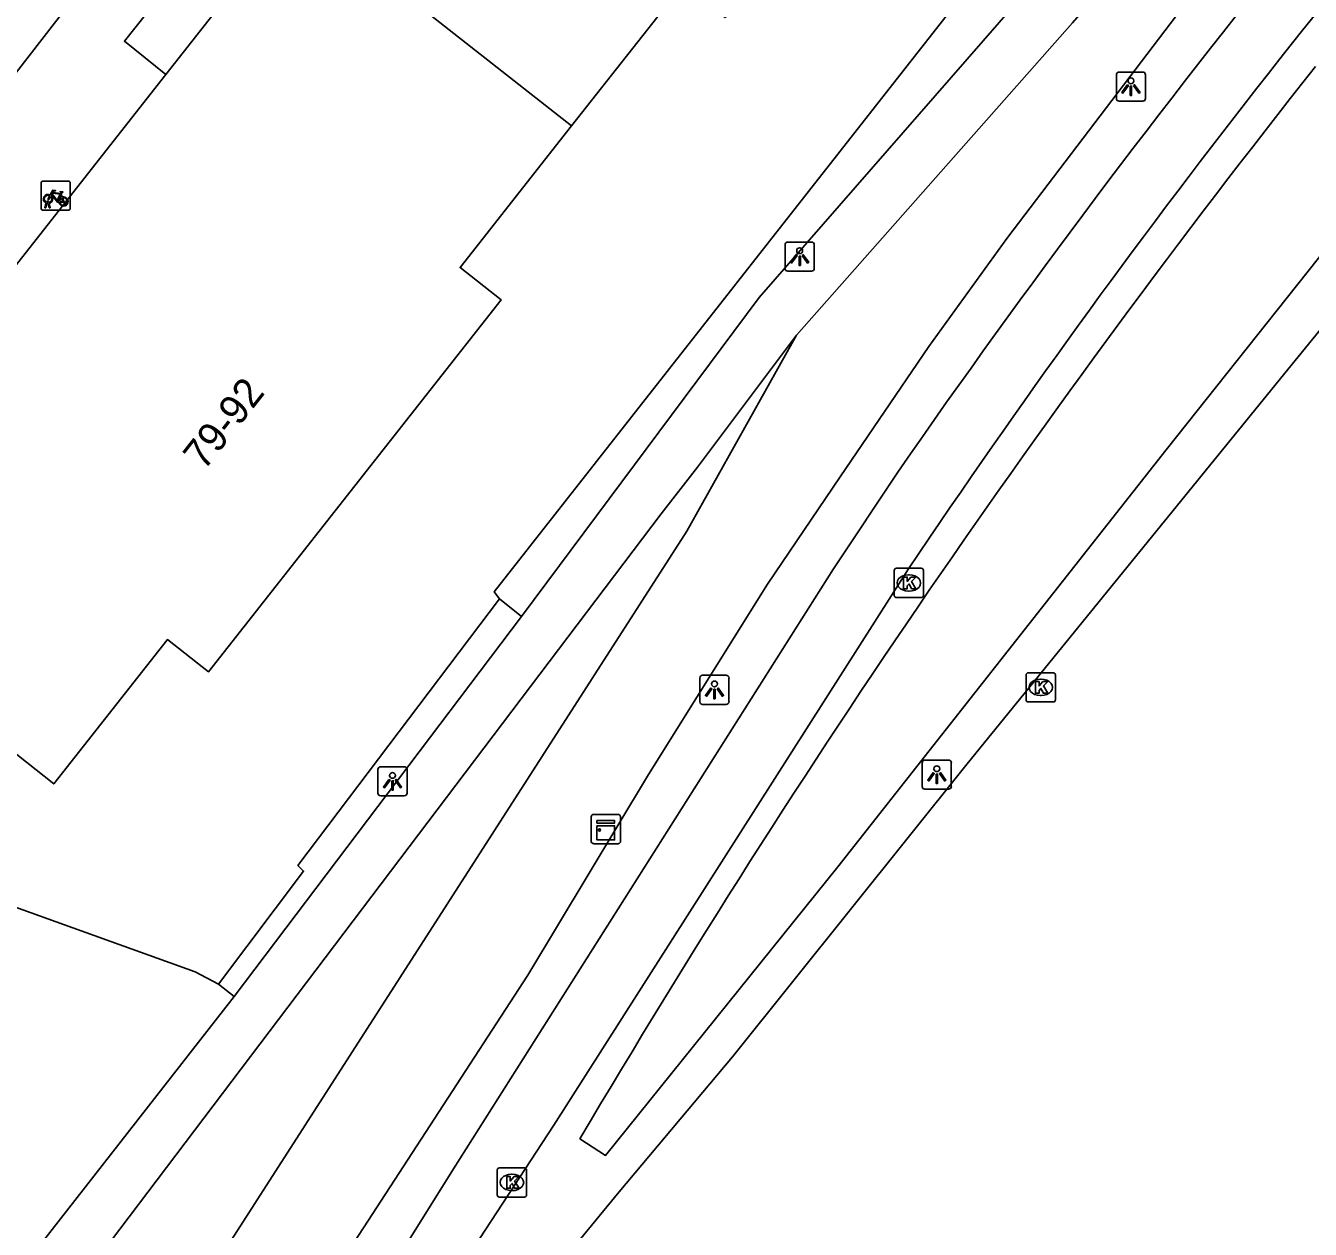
# Model space of a CAD drawing. Extents: x 160304 to 160954, y 383686 to 384161.
# Drawn here: x 160814.08 to 160858.01, y 383754.16 to 383795.32 of the extents above; entities that cross this region are included whole.
import ezdxf

# ---------------------------------------------------------------- set-up
doc = ezdxf.new("R2010")
doc.units = 0
for name, color, linetype in [('IMGEO_Fietsenrek', 7, 'Continuous'), ('IMGEO_Fietspad_open', 7, 'Continuous'), ('IMGEO_Groenvoorziening', 7, 'Continuous'), ('IMGEO_Kast', 7, 'Continuous'), ('IMGEO_Kolk', 7, 'Continuous'), ('IMGEO_Lichtpunt', 7, 'Continuous'), ('IMGEO_Pand', 7, 'Continuous'), ('IMGEO_Pand_nummerreeks', 7, 'Continuous'), ('IMGEO_Rijbaan_lokaal_gesloten', 7, 'Continuous'), ('IMGEO_Voetpad_open', 7, 'Continuous')]:
    doc.layers.add(name, color=color, linetype=linetype)

msp = doc.modelspace()

# ---------------------------------------------------------------- linework, layer by layer
at = {"layer": 'IMGEO_Fietsenrek'}
for p, q in [((160814.608, 383789.086), (160814.608, 383789.927)), ((160814.608, 383789.927), (160814.608, 383789.086)), ((160814.683, 383790.011), (160815.524, 383790.011)), ((160815.524, 383790.011), (160814.683, 383790.011)), ((160815.608, 383789.936), (160815.608, 383789.095)), ((160815.608, 383789.095), (160815.608, 383789.936)), ((160815.295, 383789.56), (160815.331, 383789.465)), ((160815.533, 383789.011), (160814.692, 383789.011)), ((160814.692, 383789.011), (160815.533, 383789.011)), ((160814.735, 383789.095), (160814.774, 383789.255)), ((160814.769, 383789.095), (160814.735, 383789.095)), ((160814.804, 383789.243), (160814.769, 383789.095)), ((160814.846, 383789.267), (160814.845, 383789.271)), ((160814.887, 383789.095), (160814.853, 383789.237)), ((160814.877, 383789.278), (160814.878, 383789.271)), ((160814.885, 383789.241), (160814.92, 383789.095)), ((160814.92, 383789.095), (160814.887, 383789.095))]:
    msp.add_line(p, q, dxfattribs=at)
for points in [[(160814.942, 383789.485), (160814.89, 383789.395), (160814.85, 383789.37), (160814.851, 383789.417), (160814.906, 383789.511)], [(160814.921, 383789.537), (160815.016, 383789.701), (160815.102, 383789.687), (160815.104, 383789.678), (160815.048, 383789.667), (160815.021, 383789.622), (160815.277, 383789.581)], [(160815.217, 383789.293), (160815.167, 383789.293), (160814.976, 383789.544), (160814.957, 383789.512)], [(160815.264, 383789.556), (160815.007, 383789.597), (160814.99, 383789.568), (160815.157, 383789.348), (160815.264, 383789.556)], [(160815.312, 383789.458), (160815.282, 383789.535), (160815.173, 383789.317), (160815.216, 383789.317)], [(160815.246, 383789.317), (160815.366, 383789.316), (160815.322, 383789.43)], [(160815.342, 383789.437), (160815.397, 383789.292), (160815.247, 383789.292)], [(160815.277, 383789.581), (160815.302, 383789.63), (160815.296, 383789.634), (160815.273, 383789.638), (160815.261, 383789.645), (160815.26, 383789.648), (160815.262, 383789.653), (160815.357, 383789.638), (160815.359, 383789.628), (160815.349, 383789.615), (160815.337, 383789.609), (160815.323, 383789.615), (160815.295, 383789.56)]]:
    msp.add_lwpolyline(points, dxfattribs=at)
for centre, radius, start, end in [((160814.686, 383789.933), 0.0779, 92.4484, 184.2845), ((160814.686, 383789.933), 0.0779, 92.4484, 184.2845), ((160815.53, 383789.933), 0.0779, 2.4484, 94.2845), ((160815.53, 383789.933), 0.0779, 2.4484, 94.2845), ((160814.848, 383789.396), 0.159, 62.6766, 242.1369), ((160814.848, 383789.396), 0.129, 63.3192, 238.903), ((160814.848, 383789.396), 0.129, 283.6043, 43.4302), ((160814.848, 383789.396), 0.159, 283.5766, 46.6042), ((160815.375, 383789.312), 0.159, 113.3408, 178.3217), ((160815.375, 383789.312), 0.159, 187.0065, 105.7708), ((160815.375, 383789.312), 0.129, 113.923, 177.9556), ((160815.375, 383789.312), 0.129, 188.6715, 104.5883), ((160814.686, 383789.089), 0.0779, 182.4484, 274.2845), ((160814.686, 383789.089), 0.0779, 182.4484, 274.2845), ((160814.828, 383789.267), 0.0499, 12.8025, 158.6934), ((160814.848, 383789.396), 0.159, 253.9967, 271.7867), ((160814.828, 383789.267), 0.0174, 12.8025, 163.4502), ((160814.848, 383789.396), 0.129, 253.415, 269.0204), ((160815.53, 383789.089), 0.0779, 272.4484, 4.2845), ((160815.53, 383789.089), 0.0779, 272.4484, 4.2845)]:
    msp.add_arc(centre, radius, start, end, dxfattribs=at)
at = {"layer": 'IMGEO_Fietspad_open'}
for points in [[(160843.924, 383780.087), (160841.708, 383776.752), (160828.708, 383756.229), (160824.825, 383750), (160824.691, 383749.789), (160821.672, 383745.431), (160821.374, 383745.047), (160818.579, 383741.442), (160805.83, 383725.823), (160799.27, 383717.787)], [(160820.118, 383739.979), (160820.253, 383740.144), (160827.186, 383750), (160828.246, 383751.753), (160832.142, 383757.714), (160844.273, 383776.749)]]:
    msp.add_lwpolyline(points, dxfattribs=at)
for centre, radius, start, end in [((161101.821, 383600.979), 313.991, 136.82328, 145.22029), ((161080.422, 383618.144), 284.468, 137.93366, 146.11352)]:
    msp.add_arc(centre, radius, start, end, dxfattribs=at)
at = {"layer": 'IMGEO_Groenvoorziening'}
for points in [[(160846.646, 383797.038), (160830.106, 383775.963), (160830.29, 383775.722)], [(160840.438, 383784.74), (160836.693, 383778.03), (160818.68, 383750), (160817.304, 383748.182)], [(160820.676, 383762.544), (160819.879, 383762.965), (160809.79, 383766.584)]]:
    msp.add_lwpolyline(points, dxfattribs=at)
at = {"layer": 'IMGEO_Kast'}
for p, q in [((160833.499, 383768.347), (160834.34, 383768.347)), ((160834.34, 383768.347), (160833.499, 383768.347)), ((160833.424, 383767.422), (160833.424, 383768.263)), ((160833.424, 383768.263), (160833.424, 383767.422)), ((160834.424, 383768.272), (160834.424, 383767.431)), ((160834.424, 383767.431), (160834.424, 383768.272)), ((160834.349, 383767.347), (160833.508, 383767.347)), ((160833.508, 383767.347), (160834.349, 383767.347))]:
    msp.add_line(p, q, dxfattribs=at)
for points in [[(160833.619, 383768.137), (160834.219, 383768.137), (160834.219, 383768.052), (160833.619, 383768.052), (160833.619, 383768.137)], [(160833.619, 383767.962), (160834.219, 383767.962), (160834.219, 383767.473), (160833.619, 383767.473), (160833.619, 383767.962)]]:
    msp.add_lwpolyline(points, dxfattribs=at)
msp.add_circle((160833.703, 383767.811), 0.0377, dxfattribs=at)
for centre, start, end in [((160833.502, 383768.269), 92.4484, 184.2845), ((160833.502, 383768.269), 92.4484, 184.2845), ((160834.346, 383768.269), 2.4484, 94.2845), ((160834.346, 383768.269), 2.4484, 94.2845), ((160834.346, 383767.425), 272.4484, 4.2845), ((160834.346, 383767.425), 272.4484, 4.2845), ((160833.502, 383767.425), 182.4484, 274.2845), ((160833.502, 383767.425), 182.4484, 274.2845)]:
    msp.add_arc(centre, 0.0779, start, end, dxfattribs=at)
at = {"layer": 'IMGEO_Kolk'}
for p, q in [((160843.782, 383775.839), (160843.782, 383776.691)), ((160843.857, 383776.765), (160844.709, 383776.765)), ((160844.783, 383776.691), (160844.783, 383775.839)), ((160844.27, 383776.545), (160844.295, 383776.545)), ((160844.293, 383775.985), (160844.268, 383775.985)), ((160844.709, 383775.765), (160843.857, 383775.765)), ((160848.368, 383773.193), (160849.22, 383773.193)), ((160848.293, 383772.267), (160848.293, 383773.119)), ((160848.781, 383772.973), (160848.806, 383772.973)), ((160849.294, 383773.119), (160849.294, 383772.267)), ((160848.804, 383772.413), (160848.779, 383772.413)), ((160849.22, 383772.193), (160848.368, 383772.193)), ((160830.21, 383755.334), (160830.21, 383756.186)), ((160830.285, 383756.26), (160831.137, 383756.26)), ((160830.698, 383756.04), (160830.723, 383756.04)), ((160831.211, 383756.186), (160831.211, 383755.334)), ((160831.137, 383755.26), (160830.285, 383755.26)), ((160830.721, 383755.48), (160830.696, 383755.48))]:
    msp.add_line(p, q, dxfattribs=at)
for points in [[(160843.782, 383775.839), (160843.782, 383776.691)], [(160843.857, 383776.765), (160844.709, 383776.765)], [(160844.783, 383776.691), (160844.783, 383775.839)], [(160844.103, 383776.465), (160844.226, 383776.465), (160844.226, 383776.314), (160844.356, 383776.465), (160844.52, 383776.465), (160844.374, 383776.314), (160844.527, 383776.065), (160844.375, 383776.065), (160844.29, 383776.229), (160844.226, 383776.162), (160844.226, 383776.065), (160844.103, 383776.065), (160844.103, 383776.465)], [(160844.709, 383775.765), (160843.857, 383775.765)], [(160848.368, 383773.193), (160849.22, 383773.193)], [(160848.293, 383772.267), (160848.293, 383773.119)], [(160848.614, 383772.893), (160848.737, 383772.893), (160848.737, 383772.742), (160848.867, 383772.893), (160849.031, 383772.893), (160848.885, 383772.742), (160849.038, 383772.493), (160848.886, 383772.493), (160848.801, 383772.657), (160848.737, 383772.59), (160848.737, 383772.493), (160848.614, 383772.493), (160848.614, 383772.893)], [(160849.294, 383773.119), (160849.294, 383772.267)], [(160849.22, 383772.193), (160848.368, 383772.193)], [(160830.21, 383755.334), (160830.21, 383756.186)], [(160830.285, 383756.26), (160831.137, 383756.26)], [(160831.211, 383756.186), (160831.211, 383755.334)], [(160830.531, 383755.96), (160830.654, 383755.96), (160830.654, 383755.809), (160830.784, 383755.96), (160830.948, 383755.96), (160830.802, 383755.809), (160830.955, 383755.56), (160830.803, 383755.56), (160830.718, 383755.724), (160830.654, 383755.657), (160830.654, 383755.56), (160830.531, 383755.56), (160830.531, 383755.96)], [(160831.137, 383755.26), (160830.285, 383755.26)]]:
    msp.add_lwpolyline(points, dxfattribs=at)
for centre, start, end in [((160843.859, 383776.689), 91.552, 178.448), ((160843.859, 383776.689), 91.552, 178.448), ((160844.707, 383776.689), 1.552, 88.448), ((160844.707, 383776.689), 1.552, 88.448), ((160843.859, 383775.841), 181.552, 268.448), ((160843.859, 383775.841), 181.552, 268.448), ((160844.707, 383775.841), 271.552, 358.448), ((160844.707, 383775.841), 271.552, 358.448), ((160848.37, 383773.117), 91.552, 178.448), ((160848.37, 383773.117), 91.552, 178.448), ((160849.218, 383773.117), 1.552, 88.448), ((160849.218, 383773.117), 1.552, 88.448), ((160848.37, 383772.269), 181.552, 268.448), ((160848.37, 383772.269), 181.552, 268.448), ((160849.218, 383772.269), 271.552, 358.448), ((160849.218, 383772.269), 271.552, 358.448), ((160830.287, 383756.184), 91.552, 178.448), ((160830.287, 383756.184), 91.552, 178.448), ((160831.135, 383756.184), 1.552, 88.448), ((160831.135, 383756.184), 1.552, 88.448), ((160830.287, 383755.336), 181.552, 268.448), ((160830.287, 383755.336), 181.552, 268.448), ((160831.135, 383755.336), 271.552, 358.448), ((160831.135, 383755.336), 271.552, 358.448)]:
    msp.add_arc(centre, 0.0765, start, end, dxfattribs=at)
for centre, major_axis, ratio, start_param, end_param in [((160844.269, 383776.265), (-0.387, 0.002), 0.722429, 4.712389, 7.853982), ((160844.294, 383776.265), (-0.39, 0.002), 0.717154, 1.570796, 4.712389), ((160848.78, 383772.693), (-0.387, 0.002), 0.722429, 4.712389, 7.853982), ((160848.805, 383772.693), (-0.39, 0.002), 0.717154, 1.570796, 4.712389), ((160830.697, 383755.76), (-0.387, 0.002), 0.722429, 4.712389, 7.853982), ((160830.722, 383755.76), (-0.39, 0.002), 0.717154, 1.570796, 4.712389)]:
    msp.add_ellipse(centre, major_axis=major_axis, ratio=ratio, start_param=start_param, end_param=end_param, dxfattribs=at)
at = {"layer": 'IMGEO_Lichtpunt'}
for p, q in [((160851.379, 383793.642), (160851.379, 383792.835)), ((160851.379, 383793.642), (160851.379, 383792.835)), ((160852.281, 383793.737), (160851.473, 383793.737)), ((160852.281, 383793.737), (160851.473, 383793.737)), ((160852.375, 383792.835), (160852.375, 383793.642)), ((160852.375, 383792.835), (160852.375, 383793.642)), ((160851.473, 383792.741), (160852.281, 383792.741)), ((160851.473, 383792.741), (160852.281, 383792.741)), ((160840.051, 383787.829), (160840.051, 383787.022)), ((160840.051, 383787.829), (160840.051, 383787.022)), ((160840.953, 383787.924), (160840.145, 383787.924)), ((160840.953, 383787.924), (160840.145, 383787.924)), ((160841.047, 383787.022), (160841.047, 383787.829)), ((160841.047, 383787.022), (160841.047, 383787.829)), ((160840.145, 383786.928), (160840.953, 383786.928)), ((160840.145, 383786.928), (160840.953, 383786.928)), ((160837.137, 383773.012), (160837.137, 383772.205)), ((160837.137, 383773.012), (160837.137, 383772.205)), ((160838.039, 383773.107), (160837.231, 383773.107)), ((160838.039, 383773.107), (160837.231, 383773.107)), ((160838.133, 383772.205), (160838.133, 383773.012)), ((160838.133, 383772.205), (160838.133, 383773.012)), ((160837.231, 383772.111), (160838.039, 383772.111)), ((160837.231, 383772.111), (160838.039, 383772.111)), ((160844.74, 383770.113), (160844.74, 383769.306)), ((160844.74, 383770.113), (160844.74, 383769.306)), ((160845.642, 383770.208), (160844.834, 383770.208)), ((160845.642, 383770.208), (160844.834, 383770.208)), ((160845.736, 383769.306), (160845.736, 383770.113)), ((160845.736, 383769.306), (160845.736, 383770.113)), ((160826.128, 383769.883), (160826.128, 383769.076)), ((160826.128, 383769.883), (160826.128, 383769.076)), ((160827.03, 383769.978), (160826.222, 383769.978)), ((160827.03, 383769.978), (160826.222, 383769.978)), ((160827.124, 383769.076), (160827.124, 383769.883)), ((160827.124, 383769.076), (160827.124, 383769.883)), ((160844.834, 383769.212), (160845.642, 383769.212)), ((160844.834, 383769.212), (160845.642, 383769.212)), ((160826.222, 383768.982), (160827.03, 383768.982)), ((160826.222, 383768.982), (160827.03, 383768.982))]:
    msp.add_line(p, q, dxfattribs=at)
for points in [[(160851.753, 383793.306), (160851.792, 383793.278), (160851.604, 383793.016), (160851.566, 383793.043), (160851.753, 383793.306)], [(160851.855, 383793.258), (160851.902, 383793.258), (160851.902, 383792.936), (160851.855, 383792.936), (160851.855, 383793.258)], [(160851.965, 383793.278), (160852.003, 383793.305), (160852.19, 383793.043), (160852.151, 383793.015), (160851.965, 383793.278)], [(160840.425, 383787.493), (160840.464, 383787.465), (160840.276, 383787.203), (160840.238, 383787.23), (160840.425, 383787.493)], [(160840.527, 383787.445), (160840.574, 383787.445), (160840.574, 383787.123), (160840.527, 383787.123), (160840.527, 383787.445)], [(160840.637, 383787.465), (160840.675, 383787.492), (160840.862, 383787.23), (160840.823, 383787.202), (160840.637, 383787.465)], [(160837.511, 383772.676), (160837.55, 383772.648), (160837.362, 383772.386), (160837.324, 383772.413), (160837.511, 383772.676)], [(160837.613, 383772.628), (160837.66, 383772.628), (160837.66, 383772.306), (160837.613, 383772.306), (160837.613, 383772.628)], [(160837.723, 383772.648), (160837.761, 383772.675), (160837.948, 383772.413), (160837.909, 383772.385), (160837.723, 383772.648)], [(160845.114, 383769.777), (160845.153, 383769.749), (160844.965, 383769.487), (160844.927, 383769.514), (160845.114, 383769.777)], [(160845.216, 383769.729), (160845.263, 383769.729), (160845.263, 383769.407), (160845.216, 383769.407), (160845.216, 383769.729)], [(160845.326, 383769.749), (160845.364, 383769.776), (160845.551, 383769.514), (160845.512, 383769.486), (160845.326, 383769.749)], [(160826.502, 383769.547), (160826.541, 383769.519), (160826.353, 383769.257), (160826.315, 383769.284), (160826.502, 383769.547)], [(160826.604, 383769.499), (160826.651, 383769.499), (160826.651, 383769.177), (160826.604, 383769.177), (160826.604, 383769.499)], [(160826.714, 383769.519), (160826.752, 383769.546), (160826.939, 383769.284), (160826.9, 383769.256), (160826.714, 383769.519)]]:
    msp.add_lwpolyline(points, dxfattribs=at)
for centre in [(160851.878, 383793.44), (160840.55, 383787.627), (160837.636, 383772.81), (160826.627, 383769.681), (160845.239, 383769.911)]:
    msp.add_circle(centre, 0.0994, dxfattribs=at)
for centre, start, end in [((160851.473, 383793.642), 90, 180), ((160851.473, 383793.642), 90, 180), ((160852.281, 383793.642), 0, 90), ((160852.281, 383793.642), 0, 90), ((160851.473, 383792.835), 180, 270), ((160851.473, 383792.835), 180, 270), ((160852.281, 383792.835), 270, 0), ((160852.281, 383792.835), 270, 360), ((160840.145, 383787.829), 90, 180), ((160840.145, 383787.829), 90, 180), ((160840.953, 383787.829), 0, 90), ((160840.953, 383787.829), 0, 90), ((160840.145, 383787.022), 180, 270), ((160840.145, 383787.022), 180, 270), ((160840.953, 383787.022), 270, 0), ((160840.953, 383787.022), 270, 360), ((160837.231, 383773.012), 90, 180), ((160837.231, 383773.012), 90, 180), ((160838.039, 383773.012), 0, 90), ((160838.039, 383773.012), 0, 90), ((160837.231, 383772.205), 180, 270), ((160837.231, 383772.205), 180, 270), ((160838.039, 383772.205), 270, 0), ((160838.039, 383772.205), 270, 360), ((160844.834, 383770.113), 90, 180), ((160844.834, 383770.113), 90, 180), ((160845.642, 383770.113), 0, 90), ((160845.642, 383770.113), 0, 90), ((160826.222, 383769.883), 90, 180), ((160826.222, 383769.883), 90, 180), ((160827.03, 383769.883), 0, 90), ((160827.03, 383769.883), 0, 90), ((160844.834, 383769.306), 180, 270), ((160844.834, 383769.306), 180, 270), ((160845.642, 383769.306), 270, 0), ((160845.642, 383769.306), 270, 360), ((160826.222, 383769.076), 180, 270), ((160826.222, 383769.076), 180, 270), ((160827.03, 383769.076), 270, 0), ((160827.03, 383769.076), 270, 360)]:
    msp.add_arc(centre, 0.0946, start, end, dxfattribs=at)
at = {"layer": 'IMGEO_Pand'}
for points in [[(160832.747, 383791.894), (160836.555, 383796.734), (160837.998, 383795.599), (160841.97, 383800.647), (160842.953, 383801.897)], [(160818.878, 383793.656), (160823.325, 383799.307)], [(160823.325, 383799.307), (160832.747, 383791.894)], [(160810.667, 383783.221), (160818.878, 383793.656)], [(160832.747, 383791.894), (160828.938, 383787.053), (160830.345, 383785.946), (160825.34, 383779.585), (160820.334, 383773.223), (160818.929, 383774.328), (160815.045, 383769.391), (160813.163, 383770.872)]]:
    msp.add_lwpolyline(points, dxfattribs=at)
at = {"layer": 'IMGEO_Rijbaan_lokaal_gesloten'}
msp.add_lwpolyline([(160892.205, 383812.465), (160886.743, 383810.447), (160884.36, 383809.262), (160882.092, 383807.87), (160881.14, 383807.197), (160876.376, 383803.73), (160871.255, 383799.379), (160868.896, 383797.108), (160866.476, 383794.701), (160864.738, 383792.813), (160863.185, 383790.855), (160857.241, 383783.559), (160846.273, 383770.081), (160838.251, 383760.058), (160834.378, 383755.442), (160829.908, 383750), (160827.882, 383747.533), (160824.143, 383742.828), (160821.256, 383739.195), (160821.207, 383739.136)], dxfattribs=at)
at = {"layer": 'IMGEO_Voetpad_open'}
for points in [[(160875.807, 383821.459), (160873.125, 383818.297), (160864.338, 383808.756), (160858.767, 383802.234), (160853.84, 383796.208), (160847.633, 383788.041), (160844.965, 383784.351), (160841.939, 383779.888), (160839.455, 383776.223), (160835.377, 383769.709), (160831.252, 383762.844), (160822.902, 383750), (160820.261, 383745.938)], [(160840.438, 383784.74), (160849.874, 383795.418), (160871.102, 383819.99)], [(160818.878, 383793.656), (160817.459, 383794.79), (160818.965, 383796.703), (160826.378, 383806.12), (160827.792, 383804.985)], [(160817.153, 383798.116), (160806.551, 383784.44), (160803.43, 383786.88), (160803.308, 383786.955), (160803.18, 383787.02), (160803.047, 383787.072), (160802.91, 383787.112), (160802.77, 383787.14), (160802.627, 383787.156), (160802.484, 383787.158), (160802.342, 383787.148), (160802.2, 383787.125)], [(160847.919, 383796.056), (160839.16, 383786.027), (160831.043, 383775.115)], [(160861.38, 383791.263), (160853.087, 383780.82), (160841.859, 383766.551), (160833.91, 383756.687), (160833.034, 383757.247)], [(160814.426, 383750.365), (160835.817, 383778.624), (160837.055, 383780.22), (160840.438, 383784.74)], [(160830.29, 383775.722), (160823.392, 383766.595), (160823.588, 383766.411), (160820.676, 383762.544)], [(160831.043, 383775.115), (160830.29, 383775.722)], [(160821.21, 383762.12), (160831.043, 383775.115)], [(160821.21, 383762.12), (160820.676, 383762.544)], [(160813.111, 383751.753), (160821.21, 383762.12)]]:
    msp.add_lwpolyline(points, dxfattribs=at)
msp.add_arc((161113.826, 383591.652), 325.984, 141.64793, 149.47039, dxfattribs=at)

# ---------------------------------------------------------------- texts
at = {"layer": 'IMGEO_Pand_nummerreeks'}
msp.add_text('79-92', height=1, rotation=51.8664, dxfattribs=at).set_placement((160820.182, 383780.077))

doc.saveas('drawing.dxf')
